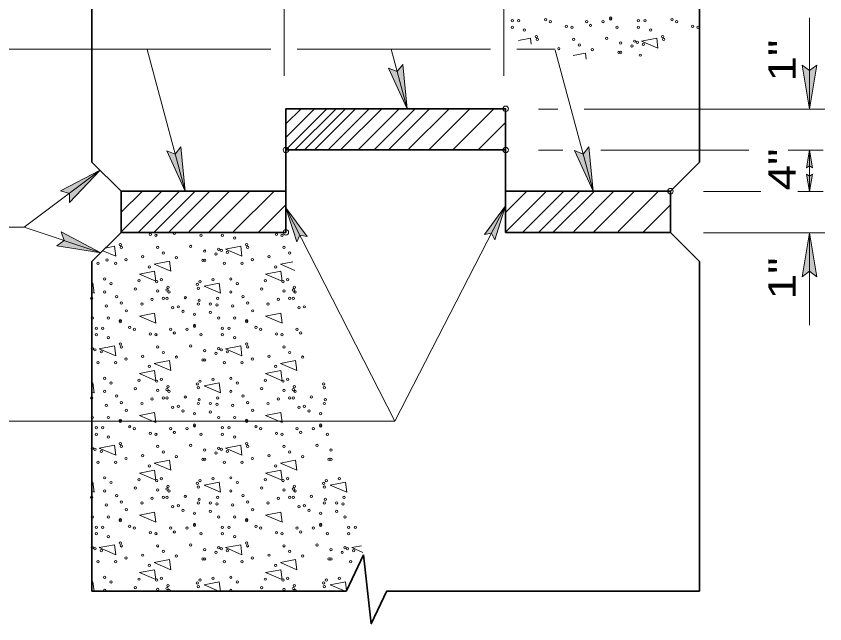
# Model space of a CAD drawing. Extents: x -43.06 to -36.2, y -1.41 to 7.25.
# Drawn here: x -41.673 to -39.906, y 2.377 to 3.704 of the extents above; entities that cross this region are included whole.
import ezdxf
from ezdxf.enums import TextEntityAlignment as Align

# ---------------------------------------------------------------- set-up
doc = ezdxf.new("R2010")
doc.units = 0
doc.header["$LTSCALE"] = 0.024
doc.header["$PDMODE"] = 32
doc.header["$PDSIZE"] = 0.012
for name, color, linetype, lineweight in [('1', 7, 'Continuous', 35), ('10', 7, 'Continuous', 13), ('12', 7, 'Continuous', 53), ('6', 7, 'Continuous', 13)]:
    doc.layers.add(name, color=color, linetype=linetype, lineweight=lineweight)

msp = doc.modelspace()

# ---------------------------------------------------------------- hatches: boundary and pattern name
at = {"layer": '10'}
for points in [[(-40.81858, 3.502), (-40.82808, 3.599), (-40.84042, 3.58317), (-40.85892, 3.59067)], [(-39.92358, 3.59733), (-39.93958, 3.50133), (-39.95558, 3.59733), (-39.93958, 3.58533)], [(-41.30342, 3.32183), (-41.31292, 3.41867), (-41.32508, 3.403), (-41.34375, 3.4105)], [(-40.41225, 3.322), (-40.42158, 3.41883), (-40.43392, 3.40317), (-40.45258, 3.41067)], [(-39.93958, 3.41133), (-39.93308, 3.37283), (-39.93958, 3.37767), (-39.94592, 3.37283)], [(-41.48892, 3.36767), (-41.55608, 3.29717), (-41.55608, 3.31717), (-41.57542, 3.32283)], [(-39.93958, 3.35467), (-39.93308, 3.3595), (-39.93958, 3.32117), (-39.94592, 3.3595)], [(-40.60325, 3.29), (-40.62708, 3.21583), (-40.63392, 3.23017), (-40.64975, 3.2275)], [(-41.08325, 3.2855), (-41.05975, 3.21117), (-41.05275, 3.22567), (-41.03708, 3.22283)], [(-41.48775, 3.1875), (-41.58392, 3.20283), (-41.56758, 3.21417), (-41.57392, 3.23317)], [(-39.92358, 3.135), (-39.93958, 3.231), (-39.95558, 3.135), (-39.93958, 3.147)]]:
    msp.add_hatch(color=256, dxfattribs=at).paths.add_polyline_path(points)

# ---------------------------------------------------------------- linework, layer by layer
at = {"layer": '1'}
for p, q in [((-41.08325, 3.412), (-40.60325, 3.412)), ((-41.08325, 3.232), (-41.08325, 3.322)), ((-40.24325, 3.322), (-40.60342, 3.322)), ((-40.24325, 3.232), (-40.24325, 3.322)), ((-41.50708, 3.16833), (-41.44342, 3.232)), ((-41.08325, 3.232), (-41.44342, 3.232)), ((-41.50708, 3.16833), (-41.50708, 2.44817))]:
    msp.add_line(p, q, dxfattribs=at)
for points in [[(-41.44342, 3.322), (-41.50708, 3.38567), (-41.50708, 4.10583)], [(-40.24325, 3.322), (-40.17958, 3.38567), (-40.17958, 4.10583)], [(-41.44342, 3.232), (-41.44342, 3.322), (-41.08325, 3.322), (-41.08325, 3.502), (-40.60325, 3.502)], [(-40.60325, 3.502), (-40.60325, 3.322), (-40.60325, 3.232)], [(-40.17958, 2.44817), (-40.17958, 3.16833), (-40.24325, 3.232), (-40.60325, 3.232)]]:
    msp.add_lwpolyline(points, dxfattribs=at)
at = {"layer": '10'}
for p, q in [((-41.08742, 3.574), (-41.08742, 4.30783)), ((-40.60742, 3.574), (-40.60742, 4.30783)), ((-39.93958, 3.701), (-39.93958, 3.50133)), ((-41.57558, 3.632), (-41.89225, 3.632)), ((-41.11625, 3.632), (-41.57558, 3.632)), ((-41.38642, 3.63167), (-41.30342, 3.32183)), ((-41.05858, 3.632), (-40.63625, 3.632)), ((-40.85342, 3.632), (-40.81858, 3.502)), ((-40.57858, 3.632), (-40.49475, 3.632)), ((-40.49475, 3.63033), (-40.41225, 3.322)), ((-40.85892, 3.59067), (-40.81858, 3.502)), ((-40.85892, 3.59067), (-40.84042, 3.58317)), ((-40.82808, 3.599), (-40.84042, 3.58317)), ((-40.82808, 3.599), (-40.81858, 3.502)), ((-39.95558, 3.59733), (-39.93958, 3.50133)), ((-39.95558, 3.59733), (-39.93958, 3.58533)), ((-39.92358, 3.59733), (-39.93958, 3.50133)), ((-39.92358, 3.59733), (-39.93958, 3.58533)), ((-40.53125, 3.50133), (-40.48908, 3.50133)), ((-40.43142, 3.50133), (-39.90592, 3.50133)), ((-41.34375, 3.4105), (-41.30342, 3.32183)), ((-41.34375, 3.4105), (-41.32508, 3.403)), ((-41.31292, 3.41867), (-41.32508, 3.403)), ((-41.31292, 3.41867), (-41.30342, 3.32183)), ((-40.53125, 3.41133), (-40.47808, 3.41133)), ((-40.45258, 3.41067), (-40.41225, 3.322)), ((-40.45258, 3.41067), (-40.43392, 3.40317)), ((-40.42158, 3.41883), (-40.43392, 3.40317)), ((-40.42158, 3.41883), (-40.41225, 3.322)), ((-40.39508, 3.41133), (-40.07225, 3.41133)), ((-39.98592, 3.41133), (-39.90942, 3.41133)), ((-39.94592, 3.37283), (-39.93958, 3.41133)), ((-39.93958, 3.32117), (-39.93958, 3.41133)), ((-39.93308, 3.37283), (-39.93958, 3.41133)), ((-39.94592, 3.37283), (-39.93958, 3.37767)), ((-39.93308, 3.37283), (-39.93958, 3.37767)), ((-41.65475, 3.24317), (-41.48892, 3.36767)), ((-41.57542, 3.32283), (-41.48892, 3.36767)), ((-41.55608, 3.29717), (-41.48892, 3.36767)), ((-39.94592, 3.3595), (-39.93958, 3.32117)), ((-39.94592, 3.3595), (-39.93958, 3.35467)), ((-39.93308, 3.3595), (-39.93958, 3.32117)), ((-39.93308, 3.3595), (-39.93958, 3.35467)), ((-41.57542, 3.32283), (-41.55608, 3.31717)), ((-41.55608, 3.29717), (-41.55608, 3.31717)), ((-40.17125, 3.32117), (-40.04608, 3.32117)), ((-39.96492, 3.32117), (-39.90942, 3.32117)), ((-40.84525, 2.81933), (-40.60325, 3.29)), ((-40.64975, 3.2275), (-40.60325, 3.29)), ((-40.62708, 3.21583), (-40.60325, 3.29)), ((-41.05975, 3.21117), (-41.08325, 3.2855)), ((-41.03708, 3.22283), (-41.08325, 3.2855)), ((-40.84525, 2.81933), (-41.08325, 3.2855)), ((-41.76208, 3.24317), (-41.65475, 3.24317)), ((-41.65475, 3.24317), (-41.48775, 3.1875)), ((-41.57392, 3.23317), (-41.48775, 3.1875)), ((-41.57392, 3.23317), (-41.56758, 3.21417)), ((-41.05975, 3.21117), (-41.05275, 3.22567)), ((-41.03708, 3.22283), (-41.05275, 3.22567)), ((-40.64975, 3.2275), (-40.63392, 3.23017)), ((-40.62708, 3.21583), (-40.63392, 3.23017)), ((-40.17125, 3.231), (-39.90592, 3.231)), ((-39.95558, 3.135), (-39.93958, 3.231)), ((-39.93958, 3.231), (-39.93958, 3.02933)), ((-39.92358, 3.135), (-39.93958, 3.231)), ((-41.58392, 3.20283), (-41.56758, 3.21417)), ((-41.58392, 3.20283), (-41.48775, 3.1875)), ((-39.95558, 3.135), (-39.93958, 3.147)), ((-39.92358, 3.135), (-39.93958, 3.147)), ((-41.86008, 2.81933), (-40.84525, 2.81933))]:
    msp.add_line(p, q, dxfattribs=at)
at = {"layer": '10', "lineweight": 35}
for p, q in [((-40.91375, 2.52767), (-40.95058, 2.44867)), ((-40.95092, 2.44817), (-41.50708, 2.44817)), ((-40.17958, 2.44817), (-40.86292, 2.44817))]:
    msp.add_line(p, q, dxfattribs=at)
at = {"layer": '10'}
for points in [[(-40.81858, 3.502), (-40.82808, 3.599), (-40.84042, 3.58317), (-40.85892, 3.59067)], [(-39.92358, 3.59733), (-39.93958, 3.50133), (-39.95558, 3.59733), (-39.93958, 3.58533)], [(-41.30342, 3.32183), (-41.31292, 3.41867), (-41.32508, 3.403), (-41.34375, 3.4105)], [(-40.41225, 3.322), (-40.42158, 3.41883), (-40.43392, 3.40317), (-40.45258, 3.41067)], [(-39.93958, 3.41133), (-39.93308, 3.37283), (-39.93958, 3.37767), (-39.94592, 3.37283)], [(-41.48892, 3.36767), (-41.55608, 3.29717), (-41.55608, 3.31717), (-41.57542, 3.32283)], [(-39.93958, 3.35467), (-39.93308, 3.3595), (-39.93958, 3.32117), (-39.94592, 3.3595)], [(-40.60325, 3.29), (-40.62708, 3.21583), (-40.63392, 3.23017), (-40.64975, 3.2275)], [(-41.08325, 3.2855), (-41.05975, 3.21117), (-41.05275, 3.22567), (-41.03708, 3.22283)], [(-41.48775, 3.1875), (-41.58392, 3.20283), (-41.56758, 3.21417), (-41.57392, 3.23317)], [(-39.92358, 3.135), (-39.93958, 3.231), (-39.95558, 3.135), (-39.93958, 3.147)]]:
    msp.add_lwpolyline(points, close=True, dxfattribs=at)
at = {"layer": '10', "lineweight": 35}
msp.add_lwpolyline([(-40.91375, 2.52767), (-40.89692, 2.37667), (-40.86275, 2.44867)], dxfattribs=at)
at = {"layer": '6'}
for p, q in [((-41.08375, 3.41233), (-40.99392, 3.502)), ((-41.08375, 3.4395), (-41.02108, 3.502)), ((-41.08258, 3.4695), (-41.05008, 3.502)), ((-41.06342, 3.41233), (-40.97375, 3.502)), ((-41.04208, 3.413), (-40.95292, 3.502)), ((-41.02075, 3.41233), (-40.93108, 3.502)), ((-40.99125, 3.41233), (-40.90158, 3.502)), ((-40.96292, 3.413), (-40.87392, 3.502)), ((-40.92475, 3.413), (-40.83592, 3.502)), ((-40.89075, 3.4125), (-40.80125, 3.502)), ((-40.85842, 3.413), (-40.76942, 3.502)), ((-40.81442, 3.41417), (-40.72675, 3.502)), ((-40.77058, 3.413), (-40.68158, 3.502)), ((-40.71742, 3.41367), (-40.62908, 3.502)), ((-40.66375, 3.41183), (-40.60325, 3.47233)), ((-41.44308, 3.233), (-41.35408, 3.322)), ((-41.44308, 3.27583), (-41.39675, 3.322)), ((-41.40492, 3.233), (-41.31592, 3.322)), ((-41.37075, 3.2325), (-41.28125, 3.322)), ((-41.33842, 3.233), (-41.24958, 3.322)), ((-41.29458, 3.23417), (-41.20675, 3.322)), ((-41.25075, 3.233), (-41.16175, 3.322)), ((-41.19758, 3.23367), (-41.10925, 3.322)), ((-40.60292, 3.233), (-40.51392, 3.322)), ((-40.60292, 3.27583), (-40.55675, 3.322)), ((-40.56475, 3.233), (-40.47575, 3.322)), ((-40.53075, 3.2325), (-40.44108, 3.322)), ((-40.49842, 3.233), (-40.40942, 3.322)), ((-40.45442, 3.23417), (-40.36658, 3.322)), ((-40.41058, 3.233), (-40.32158, 3.322)), ((-40.35742, 3.23367), (-40.26908, 3.322)), ((-41.14375, 3.23183), (-41.08325, 3.29233)), ((-40.30375, 3.23183), (-40.24325, 3.29233)), ((-41.09508, 3.1625), (-41.06792, 3.16783)), ((-41.06342, 3.14883), (-41.09508, 3.1625)), ((-40.93942, 2.54317), (-40.91842, 2.54717)), ((-40.91492, 2.53267), (-40.93942, 2.54317)), ((-41.22958, 2.44817), (-41.26208, 2.46217)), ((-40.95375, 2.44817), (-40.98625, 2.46217)), ((-41.50542, 2.44817), (-41.50708, 2.449))]:
    msp.add_line(p, q, dxfattribs=at)
for points in [[(-40.57542, 3.65117), (-40.54908, 3.65633), (-40.54742, 3.6435)], [(-40.45575, 3.6185), (-40.42892, 3.62367), (-40.42725, 3.61067)], [(-41.47758, 3.19783), (-41.45792, 3.20167), (-41.45508, 3.17967), (-41.48342, 3.19183)], [(-41.50708, 3.12017), (-41.50475, 3.12067), (-41.50192, 3.09883), (-41.50708, 3.101)], [(-41.50708, 2.90283), (-41.50475, 2.90333), (-41.50192, 2.8815), (-41.50708, 2.88367)], [(-41.50708, 2.6855), (-41.50475, 2.686), (-41.50192, 2.664), (-41.50708, 2.66633)], [(-41.50708, 2.46817), (-41.50475, 2.46867), (-41.50208, 2.44817)], [(-41.26208, 2.46217), (-41.22892, 2.46867), (-41.22625, 2.44817)], [(-40.98625, 2.46217), (-40.95308, 2.46867), (-40.95058, 2.44883)]]:
    msp.add_lwpolyline(points, dxfattribs=at)
for points in [[(-40.30642, 3.64983), (-40.27325, 3.65633), (-40.27042, 3.63433)], [(-41.21525, 3.19517), (-41.18208, 3.20167), (-41.17925, 3.17967)], [(-41.37092, 3.1625), (-41.33775, 3.169), (-41.33492, 3.14717)], [(-41.40342, 3.14067), (-41.37042, 3.14717), (-41.36742, 3.12533)], [(-41.12758, 3.14067), (-41.09458, 3.14717), (-41.09175, 3.12533)], [(-41.26208, 3.11417), (-41.22892, 3.12067), (-41.22608, 3.09883)], [(-41.40342, 3.049), (-41.37042, 3.0555), (-41.36742, 3.03367)], [(-41.12758, 3.049), (-41.09458, 3.0555), (-41.09175, 3.03367)], [(-41.49108, 2.97783), (-41.45792, 2.98433), (-41.45508, 2.96233)], [(-41.21525, 2.97783), (-41.18208, 2.98433), (-41.17925, 2.96233)], [(-41.37092, 2.94517), (-41.33775, 2.95167), (-41.33492, 2.92983)], [(-41.09508, 2.94517), (-41.06208, 2.95167), (-41.05908, 2.92983)], [(-41.40342, 2.92333), (-41.37042, 2.92983), (-41.36742, 2.90783)], [(-41.12758, 2.92333), (-41.09458, 2.92983), (-41.09175, 2.90783)], [(-41.26208, 2.89683), (-41.22892, 2.90333), (-41.22608, 2.8815)], [(-41.40342, 2.83167), (-41.37042, 2.83817), (-41.36742, 2.81633)], [(-41.12758, 2.83167), (-41.09458, 2.83817), (-41.09175, 2.81633)], [(-41.49108, 2.7605), (-41.45792, 2.767), (-41.45508, 2.745)], [(-41.21525, 2.7605), (-41.18208, 2.767), (-41.17925, 2.745)], [(-41.37092, 2.72783), (-41.33775, 2.73433), (-41.33492, 2.7125)], [(-41.09508, 2.72783), (-41.06208, 2.73433), (-41.05908, 2.7125)], [(-41.40342, 2.706), (-41.37042, 2.7125), (-41.36742, 2.6905)], [(-41.12758, 2.706), (-41.09458, 2.7125), (-41.09175, 2.6905)], [(-41.26208, 2.6795), (-41.22892, 2.686), (-41.22608, 2.664)], [(-40.98625, 2.6795), (-40.95308, 2.686), (-40.95025, 2.664)], [(-41.40342, 2.61433), (-41.37042, 2.62083), (-41.36742, 2.599)], [(-41.12758, 2.61433), (-41.09458, 2.62083), (-41.09175, 2.599)], [(-41.49108, 2.54317), (-41.45792, 2.5495), (-41.45508, 2.52767)], [(-41.21525, 2.54317), (-41.18208, 2.5495), (-41.17925, 2.52767)], [(-41.37092, 2.5105), (-41.33775, 2.517), (-41.33492, 2.495)], [(-41.09508, 2.5105), (-41.06208, 2.517), (-41.05908, 2.495)], [(-41.40342, 2.48867), (-41.37042, 2.495), (-41.36742, 2.47317)], [(-41.12758, 2.48867), (-41.09458, 2.495), (-41.09175, 2.47317)]]:
    msp.add_lwpolyline(points, close=True, dxfattribs=at)
for centre in [(-40.58885, 3.69447), (-40.57457, 3.69447), (-40.51556, 3.69647), (-40.50536, 3.69243), (-40.42594, 3.69243), (-40.39038, 3.69243), (-40.37409, 3.70055), (-40.37409, 3.69851), (-40.31304, 3.69447), (-40.29876, 3.69447), (-40.23975, 3.69647), (-40.22955, 3.69243), (-40.58885, 3.68019), (-40.56236, 3.67411), (-40.47075, 3.68223), (-40.45855, 3.68019), (-40.41782, 3.68427), (-40.35985, 3.68019), (-40.31304, 3.68019), (-40.28656, 3.67411), (-40.19495, 3.68223), (-40.18274, 3.68019), (-40.53588, 3.65982), (-40.38226, 3.65578), (-40.26008, 3.65982), (-40.53388, 3.65374), (-40.45447, 3.65374), (-40.44227, 3.6415), (-40.35173, 3.64558), (-40.32729, 3.6395), (-40.32141, 3.64974), (-40.31576, 3.6473), (-40.30212, 3.64294), (-40.25808, 3.65374), (-40.48703, 3.63338), (-40.41374, 3.63134), (-40.35577, 3.62522), (-40.35173, 3.62522), (-40.30896, 3.61914), (-41.37962, 3.2276), (-41.36741, 3.22555), (-41.32669, 3.22964), (-41.26872, 3.22555), (-41.22191, 3.22555), (-41.19543, 3.21947), (-41.10381, 3.2276), (-41.09161, 3.22555), (-41.44475, 3.20519), (-41.44275, 3.19911), (-41.36333, 3.19911), (-41.29112, 3.20115), (-41.23027, 3.19511), (-41.16894, 3.20519), (-41.16694, 3.19911), (-41.08753, 3.19911), (-41.3959, 3.17875), (-41.35113, 3.18687), (-41.2606, 3.19095), (-41.23615, 3.18487), (-41.22463, 3.19267), (-41.21099, 3.18831), (-41.12009, 3.17875), (-41.07533, 3.18687), (-41.49363, 3.1645), (-41.47408, 3.17182), (-41.45495, 3.1645), (-41.43254, 3.17263), (-41.32261, 3.17671), (-41.26464, 3.17059), (-41.2606, 3.17059), (-41.21783, 3.1645), (-41.17914, 3.1645), (-41.15674, 3.17263), (-41.38166, 3.15634), (-41.10585, 3.15634), (-41.47939, 3.13038), (-41.40406, 3.1263), (-41.35517, 3.12834), (-41.24227, 3.12834), (-41.20359, 3.13038), (-41.12825, 3.1263), (-41.07937, 3.12834), (-41.46511, 3.12018), (-41.41218, 3.10798), (-41.36537, 3.12426), (-41.34093, 3.11206), (-41.27688, 3.11814), (-41.27484, 3.11002), (-41.27076, 3.12426), (-41.1893, 3.12018), (-41.13638, 3.10798), (-41.08957, 3.12426), (-41.06512, 3.11206), (-41.47939, 3.10185), (-41.45291, 3.09169), (-41.36333, 3.1039), (-41.34297, 3.10594), (-41.33889, 3.10185), (-41.30332, 3.08965), (-41.20359, 3.10185), (-41.1771, 3.09169), (-41.08753, 3.1039), (-41.06717, 3.10594), (-41.06308, 3.10185), (-41.50788, 3.08761), (-41.44275, 3.07745), (-41.39794, 3.07541), (-41.37553, 3.08557), (-41.35113, 3.08761), (-41.34297, 3.08761), (-41.27484, 3.07541), (-41.2728, 3.08353), (-41.24835, 3.07541), (-41.23411, 3.07337), (-41.23207, 3.08761), (-41.16694, 3.07745), (-41.12213, 3.07541), (-41.09973, 3.08557), (-41.07533, 3.08761), (-41.06717, 3.08761), (-41.47531, 3.07133), (-41.43182, 3.06053), (-41.33077, 3.06725), (-41.31853, 3.06929), (-41.30836, 3.05913), (-41.24835, 3.05709), (-41.19951, 3.07133), (-41.15602, 3.06053), (-41.05496, 3.06725), (-41.04272, 3.06929), (-41.50584, 3.04485), (-41.47123, 3.04485), (-41.44475, 3.03876), (-41.44475, 3.03672), (-41.28296, 3.05301), (-41.23003, 3.04485), (-41.19543, 3.04485), (-41.16894, 3.03876), (-41.16894, 3.03672), (-41.49771, 3.02248), (-41.48343, 3.02248), (-41.42442, 3.02448), (-41.41422, 3.02044), (-41.33481, 3.02044), (-41.29924, 3.02044), (-41.28296, 3.02856), (-41.28296, 3.02652), (-41.22191, 3.02248), (-41.20763, 3.02248), (-41.14862, 3.02448), (-41.13842, 3.02044), (-41.059, 3.02044), (-41.49771, 3.0082), (-41.47123, 3.00212), (-41.37962, 3.01024), (-41.36741, 3.0082), (-41.32669, 3.01228), (-41.26872, 3.0082), (-41.22191, 3.0082), (-41.19543, 3.00212), (-41.10381, 3.01024), (-41.09161, 3.0082), (-41.05088, 3.01228), (-41.44475, 2.98784), (-41.29112, 2.9838), (-41.16894, 2.98784), (-41.50608, 2.97776), (-41.50043, 2.97531), (-41.48679, 2.97095), (-41.44275, 2.98176), (-41.36333, 2.98176), (-41.35113, 2.96951), (-41.2606, 2.97359), (-41.23615, 2.96751), (-41.23027, 2.97776), (-41.22463, 2.97531), (-41.21099, 2.97095), (-41.16694, 2.98176), (-41.08753, 2.98176), (-41.07533, 2.96951), (-41.43254, 2.95527), (-41.3959, 2.96139), (-41.32261, 2.95935), (-41.26464, 2.95323), (-41.2606, 2.95323), (-41.15674, 2.95527), (-41.12009, 2.96139), (-41.0468, 2.95935), (-41.49363, 2.94715), (-41.45495, 2.94715), (-41.38166, 2.93899), (-41.21783, 2.94715), (-41.17914, 2.94715), (-41.10585, 2.93899), (-41.47939, 2.91302), (-41.20359, 2.91302), (-41.46511, 2.90282), (-41.40406, 2.90894), (-41.36537, 2.9069), (-41.35517, 2.91098), (-41.27688, 2.90078), (-41.27076, 2.9069), (-41.24227, 2.91098), (-41.1893, 2.90282), (-41.12825, 2.90894), (-41.08957, 2.9069), (-41.07937, 2.91098), (-41.00107, 2.90078), (-41.47939, 2.8845), (-41.41218, 2.89062), (-41.36333, 2.88654), (-41.34297, 2.88858), (-41.34093, 2.8947), (-41.33889, 2.8845), (-41.27484, 2.89266), (-41.20359, 2.8845), (-41.13638, 2.89062), (-41.08753, 2.88654), (-41.06717, 2.88858), (-41.06512, 2.8947), (-41.06308, 2.8845), (-40.99903, 2.89266), (-41.50788, 2.87026), (-41.45291, 2.87434), (-41.44275, 2.8601), (-41.37553, 2.86822), (-41.35113, 2.87026), (-41.34297, 2.87026), (-41.30332, 2.8723), (-41.2728, 2.86618), (-41.23207, 2.87026), (-41.1771, 2.87434), (-41.16694, 2.8601), (-41.09973, 2.86822), (-41.07533, 2.87026), (-41.06717, 2.87026), (-41.02752, 2.8723), (-40.99699, 2.86618), (-41.47531, 2.85398), (-41.43182, 2.84317), (-41.39794, 2.85806), (-41.33077, 2.84989), (-41.31853, 2.85193), (-41.30836, 2.84177), (-41.27484, 2.85806), (-41.24835, 2.85806), (-41.23411, 2.85602), (-41.19951, 2.85398), (-41.15602, 2.84317), (-41.12213, 2.85806), (-41.05496, 2.84989), (-41.04272, 2.85193), (-41.03256, 2.84177), (-40.99903, 2.85806), (-41.50584, 2.82749), (-41.47123, 2.82749), (-41.28296, 2.83565), (-41.24835, 2.83973), (-41.23003, 2.82749), (-41.19543, 2.82749), (-41.00716, 2.83565), (-41.44475, 2.82141), (-41.44475, 2.81937), (-41.42442, 2.80713), (-41.28296, 2.81121), (-41.28296, 2.80917), (-41.16894, 2.82141), (-41.16894, 2.81937), (-41.14862, 2.80713), (-41.00716, 2.81121), (-41.00716, 2.80917), (-41.49771, 2.80513), (-41.49771, 2.79085), (-41.48343, 2.80513), (-41.41422, 2.80309), (-41.37962, 2.79289), (-41.36741, 2.79085), (-41.33481, 2.80309), (-41.32669, 2.79493), (-41.29924, 2.80309), (-41.26872, 2.79085), (-41.22191, 2.80513), (-41.22191, 2.79085), (-41.20763, 2.80513), (-41.13842, 2.80309), (-41.10381, 2.79289), (-41.09161, 2.79085), (-41.059, 2.80309), (-41.05088, 2.79493), (-41.02344, 2.80309), (-40.99291, 2.79085), (-41.47123, 2.78476), (-41.19543, 2.78476), (-41.50608, 2.7604), (-41.50043, 2.75796), (-41.48679, 2.7536), (-41.44475, 2.77048), (-41.44275, 2.7644), (-41.36333, 2.7644), (-41.29112, 2.76644), (-41.2606, 2.75624), (-41.23027, 2.7604), (-41.22463, 2.75796), (-41.21099, 2.7536), (-41.16894, 2.77048), (-41.16694, 2.7644), (-41.08753, 2.7644), (-41.01532, 2.76644), (-40.98479, 2.75624), (-41.43254, 2.73792), (-41.3959, 2.74404), (-41.35113, 2.75216), (-41.32261, 2.742), (-41.26464, 2.73588), (-41.2606, 2.73588), (-41.23615, 2.75016), (-41.15674, 2.73792), (-41.12009, 2.74404), (-41.07533, 2.75216), (-41.0468, 2.742), (-40.98883, 2.73588), (-40.98479, 2.73588), (-41.49363, 2.7298), (-41.45495, 2.7298), (-41.38166, 2.72163), (-41.21783, 2.7298), (-41.17914, 2.7298), (-41.10585, 2.72163), (-41.47939, 2.69567), (-41.46511, 2.68547), (-41.40406, 2.69159), (-41.36537, 2.68955), (-41.35517, 2.69363), (-41.27688, 2.68343), (-41.27076, 2.68955), (-41.24227, 2.69363), (-41.20359, 2.69567), (-41.1893, 2.68547), (-41.12825, 2.69159), (-41.08957, 2.68955), (-41.07937, 2.69363), (-41.00107, 2.68343), (-40.99495, 2.68955), (-40.96647, 2.69363), (-41.47939, 2.66715), (-41.41218, 2.67327), (-41.36333, 2.66919), (-41.34297, 2.67123), (-41.34093, 2.67735), (-41.33889, 2.66715), (-41.27484, 2.67531), (-41.20359, 2.66715), (-41.13638, 2.67327), (-41.08753, 2.66919), (-41.06717, 2.67123), (-41.06512, 2.67735), (-41.06308, 2.66715), (-40.99903, 2.67531), (-41.50788, 2.6529), (-41.45291, 2.65698), (-41.37553, 2.65086), (-41.35113, 2.6529), (-41.34297, 2.6529), (-41.30332, 2.65494), (-41.2728, 2.64882), (-41.23207, 2.6529), (-41.1771, 2.65698), (-41.09973, 2.65086), (-41.07533, 2.6529), (-41.06717, 2.6529), (-41.02752, 2.65494), (-40.99699, 2.64882), (-40.95627, 2.6529), (-41.47531, 2.63662), (-41.44275, 2.64274), (-41.39794, 2.6407), (-41.33077, 2.63254), (-41.31853, 2.63458), (-41.27484, 2.6407), (-41.24835, 2.6407), (-41.23411, 2.63866), (-41.19951, 2.63662), (-41.16694, 2.64274), (-41.12213, 2.6407), (-41.05496, 2.63254), (-41.04272, 2.63458), (-40.99903, 2.6407), (-40.97255, 2.6407), (-40.95831, 2.63866), (-41.43182, 2.62582), (-41.30836, 2.62442), (-41.28296, 2.6183), (-41.24835, 2.62238), (-41.15602, 2.62582), (-41.03256, 2.62442), (-41.00716, 2.6183), (-40.97255, 2.62238), (-41.50584, 2.61014), (-41.47123, 2.61014), (-41.44475, 2.60406), (-41.44475, 2.60201), (-41.23003, 2.61014), (-41.19543, 2.61014), (-41.16894, 2.60406), (-41.16894, 2.60201), (-40.95423, 2.61014), (-41.49771, 2.58777), (-41.48343, 2.58777), (-41.42442, 2.58977), (-41.41422, 2.58573), (-41.33481, 2.58573), (-41.32669, 2.57757), (-41.29924, 2.58573), (-41.28296, 2.59385), (-41.28296, 2.59181), (-41.22191, 2.58777), (-41.20763, 2.58777), (-41.14862, 2.58977), (-41.13842, 2.58573), (-41.059, 2.58573), (-41.05088, 2.57757), (-41.02344, 2.58573), (-41.00716, 2.59385), (-41.00716, 2.59181), (-40.94611, 2.58777), (-40.93182, 2.58777), (-41.49771, 2.57349), (-41.47123, 2.56741), (-41.37962, 2.57553), (-41.36741, 2.57349), (-41.26872, 2.57349), (-41.22191, 2.57349), (-41.19543, 2.56741), (-41.10381, 2.57553), (-41.09161, 2.57349), (-40.99291, 2.57349), (-40.94611, 2.57349), (-41.50608, 2.54305), (-41.44475, 2.55313), (-41.44275, 2.54705), (-41.36333, 2.54705), (-41.29112, 2.54909), (-41.23027, 2.54305), (-41.16894, 2.55313), (-41.16694, 2.54705), (-41.08753, 2.54705), (-41.01532, 2.54909), (-40.95447, 2.54305), (-41.50043, 2.54061), (-41.48679, 2.53624), (-41.3959, 2.52668), (-41.35113, 2.5348), (-41.32261, 2.52464), (-41.2606, 2.53888), (-41.23615, 2.5328), (-41.22463, 2.54061), (-41.21099, 2.53624), (-41.12009, 2.52668), (-41.07533, 2.5348), (-41.0468, 2.52464), (-40.98479, 2.53888), (-40.96035, 2.5328), (-40.94883, 2.54061), (-40.93518, 2.53624), (-41.49363, 2.51244), (-41.45495, 2.51244), (-41.43254, 2.52056), (-41.26464, 2.51852), (-41.2606, 2.51852), (-41.21783, 2.51244), (-41.17914, 2.51244), (-41.15674, 2.52056), (-40.98883, 2.51852), (-40.98479, 2.51852), (-40.94203, 2.51244), (-41.38166, 2.50428), (-41.10585, 2.50428), (-41.47939, 2.47832), (-41.40406, 2.47423), (-41.36537, 2.47219), (-41.35517, 2.47627), (-41.27076, 2.47219), (-41.24227, 2.47627), (-41.20359, 2.47832), (-41.12825, 2.47423), (-41.08957, 2.47219), (-41.07937, 2.47627), (-40.99495, 2.47219), (-40.96647, 2.47627), (-41.46511, 2.46811), (-41.41218, 2.45591), (-41.34297, 2.45387), (-41.34093, 2.45999), (-41.27688, 2.46607), (-41.27484, 2.45795), (-41.1893, 2.46811), (-41.13638, 2.45591), (-41.06717, 2.45387), (-41.06512, 2.45999), (-41.00107, 2.46607), (-40.99903, 2.45795), (-41.47939, 2.44979), (-41.36333, 2.45183), (-41.33889, 2.44979), (-41.20359, 2.44979), (-41.08753, 2.45183), (-41.06308, 2.44979)]:
    msp.add_circle(centre, 0.00252, dxfattribs=at)
for p in [(-40.60325, 3.502), (-41.08325, 3.412), (-40.60325, 3.412), (-40.24325, 3.322), (-41.08325, 3.232)]:
    msp.add_point(p, dxfattribs=at)

# ---------------------------------------------------------------- texts
at = {"layer": '12', "width": 1.25}
for s, p in [('1"', (-39.9695, 3.60729)), ('4"', (-39.9695, 3.36938)), ('1"', (-39.9695, 3.13137))]:
    msp.add_text(s, height=0.06001, rotation=90, dxfattribs=at).set_placement(p, align=Align.CENTER)

doc.saveas('drawing.dxf')
